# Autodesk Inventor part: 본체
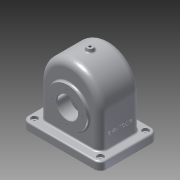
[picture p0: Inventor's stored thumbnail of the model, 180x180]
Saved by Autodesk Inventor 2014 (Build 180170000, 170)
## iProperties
Created: 2016-10
Part Number: 본체
Material: 알루미늄 6061
Document SubType Name: Modeling
Designer: USER
Density: 2.71 g/cm^3
Appearance: 알루미늄 - 평지
Mass: 1165.05 g
Surface Area: 1200.06 cm^2
Volume: 429.908 cm^3
Author: USER
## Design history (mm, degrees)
sketch "스케치1"
  geometry: L1 (0, 0)-(0, 15); L2 (0, 15)-(-150, 15); L3 (-150, 15)-(-150, 0); L4 (-150, 0)-(0, 0)
  constraints: 8 end point, 2 parallel, 1 perpendicular, 1 vertical
  dimensions: "d0" = 15 distance of L1.start L1.end; "d1" = 150 distance of L1.end L2.end
extrude "돌출1" new body sketch "스케치1" stored distance "d2" = 110; taper "d3" = 0 deg
sketch "스케치2"
  geometry: L1 (0, 0)-(-150, 0) reference; L2 (-150, 0)-(-150, 15) reference; L3 (-150, 15)-(0, 15) reference; L4 (0, 15)-(0, 0) reference; L5 (-75, 0)-(-75, 80); L6 (-17, 80)-(-17, 15); L7 (-133, 80)-(-133, 15); A1 r 58 centre (-75, 80) between (-17, 80) and (-133, 80)
  constraints: 6 end point, 2 perpendicular, 2 point on circle, 2 point on line, 2 tangent, 1 centre point, 1 coincident, 1 midpoint, 1 parallel
  dimensions: "d4" = 80 distance of L5.start L5.end; "d5" = 116 diameter of A1
extrude "돌출2" join sketch "스케치2" stored distance "d6" = 77; taper "d7" = 0 deg
sketch "스케치3"
  geometry: L1 (0, 0)-(-150, 0) reference; L2 (-150, 0)-(-150, 15) reference; L3 (-150, 15)-(-133, 15) reference; L4 (-133, 15)-(-133, 80) reference; L5 (-17, 80)-(-17, 15) reference; L6 (-17, 15)-(0, 15) reference; L7 (0, 15)-(0, 0) reference; L8 (-75, 0)-(-75, 65); C1 r 20 at (-75, 65); A1 r 58 centre (-75, 80) between (-17, 80) and (-133, 80) reference
  constraints: 2 end point, 1 centre point, 1 coincident, 1 midpoint, 1 parallel
  dimensions: "d8" = 65 distance of L8.start L8.end; "d9" = 40 diameter of C1
extrude "돌출3" cut sketch "스케치3" stored distance "d10" = 100; taper "d11" = 0 deg
sketch "스케치4"
  geometry: C1 r 20 at (75, 65) reference; C2 r 37.5 at (75, 65); 1 further point
  constraints: 1 centre point, 1 coincident
  dimensions: "d12" = 75 diameter of C2
extrude "돌출4" join sketch "스케치4" distance "d13" = 5; taper "d14" = 0 deg
sketch "스케치5"
  geometry: C1 r 20 at (75, -65) reference; C2 r 31 at (75, -65); 1 further point
  constraints: 1 centre point, 1 coincident
  dimensions: "d15" = 62 diameter of C2
extrude "돌출5" join sketch "스케치5" distance "d16" = 10; taper "d17" = 0 deg
sketch "스케치6"
  geometry: L1 (0, 0)-(-150, 0) reference; L2 (-150, 0)-(-150, 15) reference; L3 (-150, 15)-(-133, 15) reference; L4 (-133, 15)-(-133, 80) reference; L5 (-17, 80)-(-17, 15) reference; L6 (-17, 15)-(0, 15) reference; L7 (0, 15)-(0, 0) reference; L8 (-23, 80)-(-23, 0); L9 (-127, 80)-(-127, 0); C1 r 20 at (-75, 65) reference; A1 r 58 centre (-75, 80) between (-17, 80) and (-133, 80) reference; A2 r 52 centre (-75, 80) between (-23, 80) and (-127, 80)
  constraints: 4 end point, 2 point on circle, 2 point on line, 2 tangent, 1 centre point, 1 coincident, 1 parallel, 1 perpendicular
  dimensions: "d18" = 104 diameter of A2
extrude "돌출6" cut sketch "스케치6" stored distance "d19" = 67; taper "d20" = 0 deg
node "작업 평면1"
sketch "스케치7"
  geometry: L1 (-19, 87)-(-19, 77) reference; L2 (-19, 77)-(0, 77) reference; L3 (0, 77)-(0, 93.5) reference; L4 (0, 93.5)-(15, 93.5) reference; L5 (15, 93.5)-(15, 72) reference; L6 (15, 72)-(-30, 72) reference; L7 (-30, 72)-(-30, 87) reference; L8 (-30, 87)-(-19, 87) reference; L9 (-123, 0)-(-123, 77) reference; L10 (-123, 77)-(-81, 77) reference; L11 (-81, 77)-(-81, 87) reference; L12 (-81, 87)-(-70, 87) reference; L13 (-70, 87)-(-70, 72) reference; L14 (-70, 72)-(-117, 72) reference; L15 (-117, 72)-(-117, 5) reference; L16 (-117, 5)-(-70, 5) reference; L17 (-70, 5)-(-70, -5) reference; L18 (-70, -5)-(-87.5, -5) reference; L19 (-87.5, -5)-(-87.5, 0) reference; L20 (-87.5, 0)-(-123, 0) reference; L21 (15, -16.5)-(0, -16.5) reference; L22 (0, -16.5)-(0, 0) reference; L23 (0, 0)-(-12.5, 0) reference; L24 (-12.5, 0)-(-12.5, -5) reference; L25 (-12.5, -5)-(-30, -5) reference; L26 (-30, -5)-(-30, 5) reference; L27 (-30, 5)-(15, 5) reference; L28 (15, 5)-(15, -16.5) reference; L29 (-70, -5)-(-30, -5); L30 (-50, -5)-(-50, 38.5); L31 (-50, -5)-(-50, 19); L32 (-50, 19)-(-78, 19); L33 (-78, 19)-(-89.747, 5); L34 (-70, 5)-(-50, 5); 1 further point
  constraints: 12 end point, 3 perpendicular, 3 point on line, 1 collinear, 1 midpoint
  dimensions: "d21" = 24 distance of L30.start L31.end; "d22" = 28 distance of L31.end L32.end; "d23" = 50 deg angle of L33 L32
revolve "회전1" sketch "스케치7" stored, may be unused: angle "d24" = 90 deg
sketch "스케치8"
  geometry: C1 r 20 at (0, 0) reference; 1 further point
extrude "돌출7" cut sketch "스케치8" distance "d25" = 100; taper "d26" = 0 deg
sketch "스케치9"
  geometry: C1 r 37.5 at (0, 0) reference; A1 r 29 centre (0, 0) between (-29, 0) and (0, 29); 3 further points
  constraints: 4 point on circle, 1 centre point, 1 coincident
  dimensions: "d27" = 58 diameter of A1
hole "구멍1" sketch "스케치9" at (-29, 0), (0, 29), (29, 0), (0, -29) diameter "d28" = 2.459; stored, may be unused: countersink angle "d32" = 90 deg, drill point angle "d34" = 118 deg; dims "d29" = 6, "d30" = 4, "d31" = 2, "d33" = 8
sketch "스케치10"
  geometry: C1 r 31 at (0, 0) reference; A1 r 26 centre (0, 0) between (26, 0) and (0, 26); 3 further points
  constraints: 4 point on circle, 1 centre point, 1 coincident
  dimensions: "d35" = 52 diameter of A1
hole "구멍2" sketch "스케치10" at (26, 0), (0, 26), (-26, 0), (0, -26) diameter "d36" = 2.459; stored, may be unused: countersink angle "d40" = 90 deg, drill point angle "d42" = 118 deg; dims "d37" = 6, "d38" = 4, "d39" = 2, "d41" = 8
fillet "모깎기1" dims "d43" = 13
fillet "모깎기2" dims "d44" = 8
fillet "모깎기3" dims "d45" = 12
sketch "스케치11"
  geometry: A1 r 12 centre (0, 98) between (0, 110) and (-12, 98) reference; A2 r 12 centre (0, 12) between (-12, 12) and (0, 0) reference; A3 r 12 centre (126, 12) between (126, 0) and (138, 12) reference; A4 r 12 centre (126, 98) between (138, 98) and (126, 110) reference; 1 further point
hole "구멍3" sketch "스케치11" at (0, 98), (0, 12), (126, 98), (126, 12) diameter "d46" = 5; stored, may be unused: countersink angle "d50" = 90 deg, drill point angle "d52" = 118 deg; dims "d47" = 6, "d48" = 12, "d49" = 5, "d51" = 20
fillet "모깎기4" dims "d53" = 3
sketch "스케치12"
  geometry: L1 (-127, 80)-(-127, 0) reference; L2 (-127, 0)-(-150, 0) reference; L3 (-150, 0)-(-150, 12) reference; L4 (-147, 15)-(-136, 15) reference; L5 (-133, 18)-(-133, 80) reference; L6 (-17, 80)-(-17, 18) reference; L7 (-14, 15)-(-3, 15) reference; L8 (0, 12)-(0, 0) reference; L9 (0, 0)-(-23, 0) reference; L10 (-23, 0)-(-23, 80) reference; L11 (-23, 0)-(-127, 0); L12 (-75, 144)-(-81, 144); L13 (-81, 144)-(-82.136, 137.559); L14 (-75, 0)-(-75, 132); L15 (-75, 138)-(-75, 144); A1 r 52 centre (-75, 80) between (-23, 80) and (-127, 80) reference; A2 r 3 centre (-147, 12) between (-147, 15) and (-150, 12) reference; A3 r 3 centre (-136, 18) between (-136, 15) and (-133, 18) reference; A4 r 58 centre (-75, 80) between (-17, 80) and (-133, 80) reference; A5 r 3 centre (-14, 18) between (-17, 18) and (-14, 15) reference; A6 r 3 centre (-3, 12) between (0, 12) and (-3, 15) reference
  constraints: 10 end point, 4 perpendicular, 3 point on circle, 1 collinear, 1 midpoint
  dimensions: "d54" = 144 distance of L14.start L12.start; "d55" = 6 distance of L12.start L12.end
revolve "회전2" sketch "스케치12" stored, may be unused: angle "d57" = 90 deg
sketch "스케치13"
  geometry: C1 r 6 at (0, 0) reference; 1 further point
hole "구멍4" sketch "스케치13" at (0, 0) diameter "d58" = 4.459; stored, may be unused: countersink angle "d62" = 90 deg, drill point angle "d64" = 118 deg; dims "d59" = 20, "d60" = 4, "d61" = 2, "d63" = 20
fillet "모깎기5" dims "d65" = 3
chamfer "모따기1" distance "d66" = 1; stored, may be unused: second distance "d67" = 2, angle "d68" = 45 deg
node "작업 평면2"
sketch "스케치14"
  geometry: L1 (80, -17.5)-(80, 68.5) reference; L2 (80, 25.5)-(40, 25.5); L3 (36.398, 0.613)-(36.398, 50.387); L4 (36.398, 50.387)-(43.602, 50.387); L5 (43.602, 50.387)-(43.602, 0.613); L6 (43.602, 0.613)-(36.398, 0.613); 2 further points
  constraints: 2 end point, 1 coincident, 1 perpendicular, 2 other
  dimensions: "d70" = 40 distance of L2.start L2.end
feature "엠보싱1" sketch "스케치14" dims "d8" = 65, "d9" = 40, "d71" = 0.5, "d72" = 0
node "솔리드1"
node "절단 모서리 투영1"
node "절단 모서리 투영2"
node "절단 모서리 투영3"
node "절단 모서리 투영4"
node "절단 모서리 투영5"
other parameters: "d69" = 85.5
